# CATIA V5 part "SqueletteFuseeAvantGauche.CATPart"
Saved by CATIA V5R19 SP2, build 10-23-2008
Part number: SqueletteFuseeAvantGauche
Bounding box of the stored display mesh (mm): x 577.235 to 677.235, y -37.099 to -30.099, z -267.206 to -167.206
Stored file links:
  D:\Mes Documents\ressource\CATIA\Ensemble Catia\Voiture_Telecommmande\SchemaCinematiqueFinal\SqueletteFuseeAvantGauche.CATPart
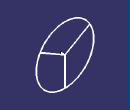
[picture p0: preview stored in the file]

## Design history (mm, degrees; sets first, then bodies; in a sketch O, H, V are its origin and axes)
AxisSystem1: origin (0, 0, 0), X (1, 0, 0), Y (0, 1, 0), Z (0, 0, 1)
Set1
  Point1 to Point3: stored without definition
  Line1: stored without definition
  Point4: stored without definition
  Line2: stored without definition
  Plane1: stored without definition
  Sketch1 on Plane1, origin (0, -30.1025, -0.0004), H (-1, 0, 0), V (0, 0, 1)
    circle A1 centre (-627.2353, -217.2052) radius 50
    point P1 (-627.2353, -217.2052)
    reference projected point E1 (-627.2353, -217.2052) from vertex of Line2
    line L1 (-627.2353, -217.2052) -> (-583.9341, -192.2052)
    point P2 (-583.9341, -192.2052)
    line L2 (-627.2353, -217.2052) -> (-670.5366, -192.2052)
    point P3 (-670.5366, -192.2052)
    line L3 (-627.2353, -217.2052) -> (-627.2353, -267.2052)
    point P4 (-627.2353, -217.2052)
    point P5 (-627.2353, -267.2052)
    radius A1 = 50
    angle L3 L1 = 120
    angle L1 L2 = 120
    coincidence: P1 E1, P2 A1, P3 A1, P4 L2, P5 A1
    vertical: L3 V
Body1 (main body)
